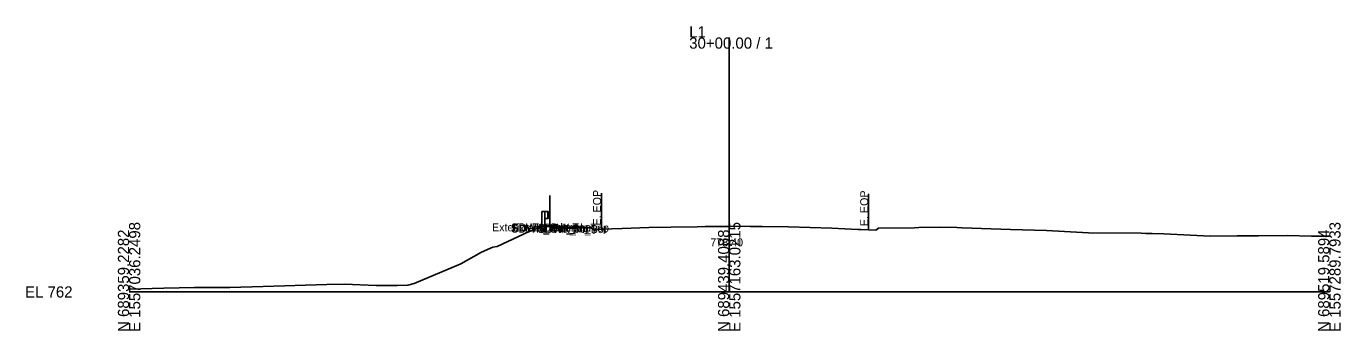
# Model space of a CAD drawing. Extents: x -26 to 2603, y -3010 to 9589.
# Drawn here: x 974.3 to 1302.8, y 3490.3 to 3566.4 of the extents above; entities that cross this region are included whole.
import ezdxf

# ---------------------------------------------------------------- set-up
doc = ezdxf.new("R2010")
doc.units = 0
for name, color, linetype in [('Default', 7, 'Continuous'), ('Exist Cross Section Cell', 7, 'Continuous'), ('Exist XS Center Line Elevation Label', 7, 'Continuous'), ('Exist XS Ground Line', 7, 'Continuous'), ('Prop CMT Conc Surface', 7, 'Continuous'), ('Prop CMT Concrete Structures', 7, 'Continuous'), ('Prop CMT Slope Grass', 7, 'Continuous'), ('Prop XS Earthwork Shape', 7, 'Continuous'), ('Prop XS Label Text', 7, 'Continuous'), ('Scratch_Level_1', 7, 'Continuous'), ('Typical Guardrail CELL', 7, 'Continuous')]:
    doc.layers.add(name, color=color, linetype=linetype)

msp = doc.modelspace()

# ---------------------------------------------------------------- linework, layer by layer
at = {"layer": 'Exist Cross Section Cell'}
for p, q in [((1150, 3500), (1150, 3563.62)), ((1000, 3500), (1150, 3500)), ((1150, 3500), (1300, 3500))]:
    msp.add_line(p, q, dxfattribs=at)
at = {"layer": 'Exist XS Ground Line'}
msp.add_lwpolyline([(1000, 3500.72), (1008.67, 3500.96), (1016.35, 3501.13), (1025.17, 3501.09), (1033.49, 3501.36), (1049.45, 3501.83), (1053.81, 3501.92), (1061.75, 3501.59), (1067, 3501.6), (1069.71, 3501.72), (1071.27, 3502.1), (1082.94, 3507.01), (1088.07, 3509.97), (1090.88, 3511.22), (1091.98, 3511.39), (1100.01, 3515.08), (1103.02, 3516.29), (1103.54, 3516.39), (1107.77, 3516.27), (1109.48, 3516.22), (1111.53, 3516.05), (1111.94, 3516.05), (1115.49, 3516.04), (1116.07, 3515.6), (1116.92, 3515.64), (1118.06, 3515.68), (1123.23, 3515.85), (1129.91, 3516.07), (1135.37, 3516.18), (1141.99, 3516.29), (1143.97, 3516.32), (1146.42, 3516.36), (1148.8, 3516.39), (1150, 3516.4), (1151.44, 3516.42), (1155.2, 3516.39), (1158.26, 3516.35), (1164.82, 3516.24), (1170.25, 3516.12), (1175.68, 3515.91), (1182.16, 3515.64), (1182.79, 3515.62), (1184.85, 3515.53), (1186.63, 3515.47), (1187.32, 3515.94), (1196.35, 3516.01), (1197.36, 3516.15), (1202.61, 3516.17), (1206.88, 3516.15), (1208.25, 3516.06), (1220.33, 3515.59), (1229.27, 3515.34), (1239.82, 3514.8), (1252.94, 3514.72), (1254.15, 3514.64), (1255.7, 3514.59), (1258.67, 3514.51), (1270.25, 3513.93), (1277, 3514.02), (1282.3, 3514.03), (1289.48, 3514.07), (1295.56, 3513.98), (1300, 3513.94)], dxfattribs=at)
at = {"layer": 'Prop CMT Conc Surface'}
msp.add_line((1111.57, 3516.16), (1106.57, 3516.3), dxfattribs=at)
at = {"layer": 'Prop CMT Concrete Structures'}
msp.add_line((1111.57, 3515.82), (1106.57, 3515.97), dxfattribs=at)
for points in [[(1106.57, 3515.97), (1106.57, 3516.3)], [(1111.57, 3516.16), (1111.57, 3515.82)]]:
    msp.add_lwpolyline(points, dxfattribs=at)
at = {"layer": 'Prop CMT Slope Grass'}
msp.add_line((1111.57, 3516.16), (1115.49, 3516.04), dxfattribs=at)
at = {"layer": 'Prop XS Earthwork Shape'}
for points in [[(1108.42, 3516.25), (1106.57, 3516.3), (1107.77, 3516.27)], [(1111.57, 3516.05), (1111.57, 3515.82), (1106.57, 3515.97), (1106.57, 3516.3), (1108.42, 3516.25), (1109.48, 3516.22), (1111.53, 3516.05)], [(1111.57, 3516.16), (1111.57, 3516.05), (1111.94, 3516.05), (1115.49, 3516.04)]]:
    msp.add_lwpolyline(points, close=True, dxfattribs=at)
at = {"layer": 'Prop XS Label Text'}
for p, q in [((1118.06, 3524.68), (1118.06, 3515.68)), ((1184.85, 3524.53), (1184.85, 3515.53))]:
    msp.add_line(p, q, dxfattribs=at)
at = {"layer": 'Scratch_Level_1'}
msp.add_line((1105.13, 3516.6), (1105.13, 3524.11), dxfattribs=at)
at = {"layer": 'Typical Guardrail CELL'}
for p, q in [((1103.9, 3520.12), (1103.15, 3520.12)), ((1103.15, 3520.12), (1103.15, 3516.39)), ((1103.9, 3520.12), (1103.9, 3516.39)), ((1103.9, 3520.12), (1104.64, 3520.12)), ((1104.64, 3520.12), (1104.64, 3518.38)), ((1104.64, 3520.12), (1105.08, 3519.81)), ((1104.64, 3519.32), (1105.08, 3519.62)), ((1104.64, 3519.25), (1104.64, 3519.32)), ((1104.64, 3519.25), (1104.64, 3519.18)), ((1104.64, 3519.18), (1105.08, 3518.87)), ((1104.64, 3518.38), (1105.08, 3518.68)), ((1103.9, 3516.39), (1103.15, 3516.39)), ((1103.15, 3516.39), (1103.15, 3514.88)), ((1103.9, 3518.38), (1104.64, 3518.38)), ((1103.9, 3516.39), (1103.9, 3514.88))]:
    msp.add_line(p, q, dxfattribs=at)
for centre, start, end in [((1105.01, 3519.72), 304.9888, 54.997), ((1105.01, 3518.78), 304.9634, 54.9941)]:
    msp.add_arc(centre, 0.116, start, end, dxfattribs=at)

# ---------------------------------------------------------------- texts
at = {"layer": 'Default'}
for s, height, p in [('Exterior Boundary', 2, (1090.71, 3515.15)), ('SDWK_Out_Top', 2, (1095.5, 3515.15)), ('SDWK_Out_Bot', 2, (1095.53, 3514.82)), ('Exterior Boundary', 2, (1095.71, 3515.05)), ('SDWK_In_Top', 2, (1102.12, 3515.05)), ('SDWK_In_Bot', 2, (1102.15, 3514.72)), ('-', 0.0001, (1000, 3500))]:
    msp.add_text(s, height=height, dxfattribs=at).set_placement(p)
at = {"layer": 'Exist Cross Section Cell'}
for s, p in [('L1', (1140, 3563.62)), ('30+00.00 / 1', (1140, 3560.82)), ('EL 762', (974, 3498.6))]:
    msp.add_text(s, height=2.8, dxfattribs=at).set_placement(p)
for s, p in [('N 689359.2282', (1000, 3490)), ('E 1557036.2498', (1002.8, 3490)), ('N 689439.4088', (1150, 3490)), ('E 1557163.0215', (1152.8, 3490)), ('N 689519.5894', (1300, 3490)), ('E 1557289.7933', (1302.8, 3490))]:
    msp.add_text(s, height=2.8, rotation=90, dxfattribs=at).set_placement(p)
at = {"layer": 'Exist XS Center Line Elevation Label'}
msp.add_text('778.40', height=2, dxfattribs=at).set_placement((1145.28, 3511.4))
at = {"layer": 'Prop XS Label Text'}
for p in [(1117.96, 3516.6), (1184.75, 3516.45)]:
    msp.add_text('E. EOP', height=2, rotation=90, dxfattribs=at).set_placement(p)

doc.saveas('drawing.dxf')
